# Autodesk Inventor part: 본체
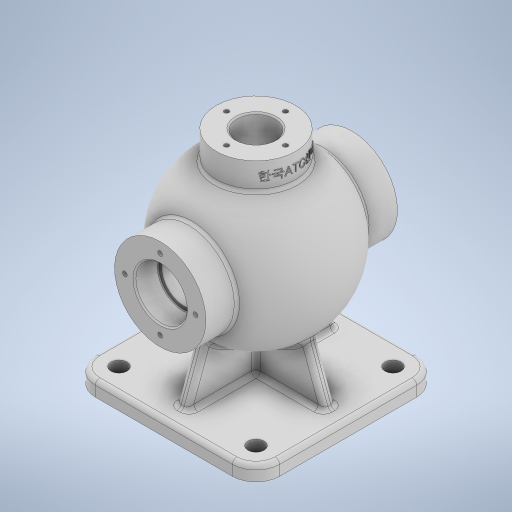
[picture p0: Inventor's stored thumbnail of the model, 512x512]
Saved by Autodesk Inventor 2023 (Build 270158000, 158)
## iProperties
Created: 2023-07
Part Number: 본체
Material: 일반
Document SubType Name: Modeling
Designer: Owner
Density: 1 g/cm^3
Appearance: 기본값
Author: Owner
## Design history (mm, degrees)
sketch "스케치1"
  geometry: L1 (-62.5, 62.5)-(62.5, 62.5); L2 (62.5, 62.5)-(62.5, -62.5); L3 (62.5, -62.5)-(-62.5, -62.5); L4 (-62.5, -62.5)-(-62.5, 62.5); L5 (-62.5, 62.5)-(62.5, -62.5); L6 (62.5, 62.5)-(-62.5, -62.5); 1 further point
  constraints: 12 end point, 2 midpoint, 2 parallel, 1 horizontal, 1 perpendicular
  dimensions: "d0" = 125 distance of L2.end L3.end; "d1" = 125 distance of L1.end L2.end
extrude "돌출1" new body sketch "스케치1" distance "d2" = 10; taper "d3" = 0 deg
fillet "모깎기1" dims "d4" = 16
fillet "모깎기2" dims "d5" = 3
sketch "스케치2"
  geometry: L1 (7, -62.5)-(0, -62.5) reference; L2 (0, -62.5)-(0, 62.5) reference; L3 (0, 62.5)-(7, 62.5) reference; L4 (10, 59.5)-(10, -59.5) reference; L5 (85, 65)-(85, -65); L6 (85, 65)-(116, 65); L7 (116, 65)-(116, 44.215); L8 (116, -44.215)-(116, -65); L9 (116, -65)-(85, -65); A1 r 3 centre (7, -59.5) between (7, -62.5) and (10, -59.5) reference; A2 r 3 centre (7, 59.5) between (10, 59.5) and (7, 62.5) reference; A3 r 54 centre (85, 0) between (116, -44.215) and (116, 44.215); 3 further points
  constraints: 10 end point, 2 midpoint, 2 perpendicular, 2 point on circle, 2 vertical, 1 centre point, 1 coincident, 1 horizontal, 1 horizontal alignment
  dimensions: "d6" = 130 distance of L5.start L5.end; "d7" = 85 distance between parallel lines of L2 L5; "d8" = 54 radius of A3; "d9" = 62 diameter of L7 L5; "d10" = 62 diameter of L8 L5
revolve "회전1" sketch "스케치2" stored, may be unused: angle "d11" = 90 deg
sketch "스케치3"
  geometry: L1 (7, -62.5)-(0, -62.5) reference; L2 (0, -62.5)-(0, 62.5) reference; L3 (0, 62.5)-(7, 62.5) reference; L4 (10, 59.5)-(10, -59.5) reference; L5 (54, 65)-(116, 65) reference; L6 (116, 65)-(116, 44.215) reference; L7 (116, -44.215)-(116, -65) reference; L8 (116, -65)-(54, -65) reference; L9 (54, -65)-(54, -44.215) reference; L10 (54, 44.215)-(54, 65) reference; L11 (10, 46.5)-(10, -46.5) reference; L12 (10, 50.5)-(55, 34.121); L13 (55, 34.121)-(55, -34.121); L14 (55, -34.121)-(10, -50.5); A1 r 3 centre (7, -59.5) between (7, -62.5) and (10, -59.5) reference; A2 r 3 centre (7, 59.5) between (10, 59.5) and (7, 62.5) reference; A3 r 54 centre (85, 0) between (116, -44.215) and (116, 44.215) reference; A4 r 54 centre (85, 0) between (54, 44.215) and (54, -44.215) reference; 7 further points
  constraints: 6 end point, 2 midpoint, 2 point on line, 1 equal length, 1 horizontal alignment, 1 parallel
  dimensions: "d12" = 20 deg angle of L12 L3; "d13" = 12 vertical distance of L2.end L12.start; "d14" = 55 distance between parallel lines of L2 L13
extrude "돌출2" join sketch "스케치3" stored distance "d15" = 8; taper "d16" = 0 deg
sketch "스케치4"
  geometry: L1 (-59.5, 10)-(-4, 10) reference; L2 (-4, 10)-(-4, 31.148) reference; L3 (4, 31.148)-(4, 10) reference; L4 (4, 10)-(59.5, 10) reference; L5 (62.5, 7)-(62.5, 0) reference; L6 (62.5, 0)-(-62.5, 0) reference; L7 (-62.5, 0)-(-62.5, 7) reference; L8 (-37.385, 46.034)-(-50.5, 10); L9 (-46.5, 10)-(46.5, 10) reference; A1 r 3 centre (-59.5, 7) between (-59.5, 10) and (-62.5, 7) reference; A2 r 3 centre (59.5, 7) between (62.5, 7) and (59.5, 10) reference; A3 r 54 centre (0, 85) between (4, 31.148) and (-4, 31.148) reference; 1 further point
  constraints: 2 end point, 1 point on circle, 1 point on line
  dimensions: "d17" = 20 deg angle of L7 L8; "d18" = 12 distance from line of L7 L8.end
feature "리브1" sketch "스케치4" dims "d19" = 1, "d20" = 8, "d21" = 0, "d22" = 0, "d23" = 1, "d24" = 1
fillet "모깎기3" dims "d25" = 3
fillet "모깎기4" dims "d26" = 3
fillet "모깎기5" dims "d27" = 3
sketch "스케치5"
  geometry: L1 (0, -62.5)-(0, 62.5) reference; L2 (0, 62.5)-(7, 62.5) reference; L3 (10, 59.5)-(10, 52.601) reference; L4 (11.974, 49.782)-(44.231, 38.041) reference; L5 (54, 45.749)-(54, 65) reference; L6 (54, 65)-(116, 65) reference; L7 (116, 65)-(116, 45.749) reference; L8 (116, -45.749)-(116, -65) reference; L9 (116, -65)-(54, -65) reference; L10 (54, -65)-(54, -45.749) reference; L11 (44.231, -38.041)-(11.974, -49.782) reference; L12 (10, -52.601)-(10, -59.5) reference; L13 (7, -62.5)-(0, -62.5) reference; L14 (54, 65)-(116, 65) reference; L15 (85, 65)-(85, -65); L16 (54, -65)-(116, -65) reference; L17 (102.5, 65)-(102.5, 49); L18 (102.5, 49)-(100, 49); L19 (100, 49)-(100, 41.364); L20 (100, -41.364)-(100, -49); L21 (100, -49)-(102.5, -49); L22 (102.5, -49)-(102.5, -65); A1 r 3 centre (7, 59.5) between (10, 59.5) and (7, 62.5) reference; A2 r 3 centre (13, 52.601) between (10, 52.601) and (11.974, 49.782) reference; A3 r 3 centre (45.257, 40.86) between (44.231, 38.041) and (47.349, 38.709) reference; A4 r 54 centre (85, 0) between (52.789, 43.341) and (47.349, 38.709) reference; A5 r 3 centre (51, 45.749) between (52.789, 43.341) and (54, 45.749) reference; A6 r 3 centre (119, 45.749) between (116, 45.749) and (117.211, 43.341) reference; A7 r 54 centre (85, 0) between (117.211, -43.341) and (117.211, 43.341) reference; A8 r 3 centre (119, -45.749) between (117.211, -43.341) and (116, -45.749) reference; A9 r 3 centre (51, -45.749) between (54, -45.749) and (52.789, -43.341) reference; A10 r 54 centre (85, 0) between (47.349, -38.709) and (52.789, -43.341) reference; A11 r 3 centre (45.257, -40.86) between (47.349, -38.709) and (44.231, -38.041) reference; A12 r 3 centre (13, -52.601) between (11.974, -49.782) and (10, -52.601) reference; A13 r 3 centre (7, -59.5) between (7, -62.5) and (10, -59.5) reference; A14 r 44 centre (85, 0) between (100, -41.364) and (100, 41.364); 5 further points
  constraints: 14 end point, 5 perpendicular, 2 equal length, 2 midpoint, 2 point on circle, 2 point on line, 2 vertical, 1 centre point, 1 vertical alignment
  dimensions: "d28" = 44 radius of A14; "d29" = 16 distance of L17.start L17.end; "d30" = 35 diameter of L17 L15; "d31" = 30 diameter of L19 L15
revolve "회전2" sketch "스케치5" stored, may be unused: angle "d32" = 90 deg
node "작업 평면1"
sketch "스케치6"
  geometry: C1 r 27 at (0, 0); C2 r 13 at (0, 0); 1 further point
  constraints: 2 centre point, 2 coincident
  dimensions: "d34" = 54 diameter of C1; "d35" = 26 diameter of C2
extrude "돌출3" join sketch "스케치6" stored distance "d36" = 8; taper "d37" = 0 deg
extrude "돌출4" cut sketch "스케치6" stored distance "d38" = 10; taper "d39" = 0 deg
fillet "모깎기6" dims "d40" = 3
chamfer "모따기1" distance "d41" = 1; stored, may be unused: second distance "d42" = 2, angle "d43" = 45 deg
sketch "스케치7"
  geometry: C1 r 5.5 at (-46.5, 46.5); C2 r 5.5 at (-46.5, -46.5); A1 r 13 centre (-46.5, 46.5) between (-46.5, 59.5) and (-59.5, 46.5) reference; A2 r 13 centre (-46.5, -46.5) between (-59.5, -46.5) and (-46.5, -59.5) reference; 1 further point
  constraints: 2 centre point, 2 coincident, 1 equal radius
  dimensions: "d44" = 11 diameter of C1
extrude "돌출5" cut sketch "스케치7" extent not by distance; stored distance "d45" = 0; taper "d46" = 0 deg
sketch "스케치8"
  geometry: C1 r 31 at (0, 0) reference; 2 further points
  constraints: 1 vertical alignment
  dimensions: "d47" = 24 distance of C1.centre point (0, 24)
hole "구멍1" sketch "스케치8" at (0, 24) diameter "d48" = 3.242; stored, may be unused: countersink angle "d52" = 90 deg, drill point angle "d54" = 118 deg; dims "d49" = 12, "d50" = 4, "d51" = 2, "d53" = 15
sketch "스케치9"
  geometry: C1 r 27 at (0, 0) reference; 1 further point
  constraints: 1 vertical alignment
  dimensions: "d58" = 20 distance of C1.centre point (0, 20)
hole "구멍2" sketch "스케치9" at (0, 20) diameter "d59" = 3.242; stored, may be unused: countersink angle "d63" = 90 deg, drill point angle "d65" = 118 deg; dims "d60" = 9, "d61" = 4, "d62" = 2, "d64" = 11
node "작업 평면2"
sketch "스케치10"
  geometry: L1 (-150, -62.5)-(-150, 62.5) reference; L2 (-150, 62.5)-(-143, 62.5) reference; L3 (-140, 59.5)-(-140, 7) reference; L4 (-137, 4)-(-114.709, 4) reference; L5 (-80.232, 45.749)-(-80.232, 65) reference; L6 (-80.232, 65)-(-49.768, 65) reference; L7 (-49.768, 65)-(-49.768, 45.749) reference; L8 (-49.768, -45.749)-(-49.768, -65) reference; L9 (-49.768, -65)-(-80.232, -65) reference; L10 (-80.232, -65)-(-80.232, -45.749) reference; L11 (-114.709, -4)-(-137, -4) reference; L12 (-140, -7)-(-140, -59.5) reference; L13 (-143, -62.5)-(-150, -62.5) reference; L14 (0, 0)-(-16.534, 0) reference; L15 (0, -27)-(0, 27) reference; C1 r 34.742 at (-65, 0) reference; A1 r 3 centre (-143, 59.5) between (-140, 59.5) and (-143, 62.5) reference; A2 r 3 centre (-137, 7) between (-140, 7) and (-137, 4) reference; A3 r 46.765 centre (-65, 0) between (-82.565, 43.341) and (-111.293, 6.632) reference; A4 r 46.765 centre (-65, 0) between (-19.084, 8.874) and (-47.435, 43.341) reference; A5 r 46.765 centre (-65, 0) between (-47.435, -43.341) and (-19.084, -8.874) reference; A6 r 46.765 centre (-65, 0) between (-111.293, -6.632) and (-82.565, -43.341) reference; A7 r 3 centre (-137, -7) between (-137, -4) and (-140, -7) reference; A8 r 3 centre (-143, -59.5) between (-143, -62.5) and (-140, -59.5) reference; 2 further points
  constraints: 1 horizontal alignment, 9 other
  dimensions: "d69" = 9 distance from line of L15 point (-9, 0)
feature "엠보싱1" sketch "스케치10" dims "d0" = 125, "d1" = 125, "d70" = 0.5, "d71" = 0
fillet "모깎기7" dims "d72" = 0.6
feature "Ǌ耀ǌ耀ǎ耀ǐ耀ǒ耀ǔ耀ǖ耀ǘ耀" dims "d0" = 125, "d1" = 125, "d2" = 10, "d3" = 0, "d4" = 16, "d5" = 3, "d6" = 130, "d7" = 85, "d8" = 54, "d9" = 62, "d10" = 62, "d11" = 90 deg, "d12" = 20 deg, "d13" = 12, "d14" = 55, "d15" = 8, "d16" = 0, "d17" = 20 deg, "d18" = 12, "d19" = 1, "d20" = 8, "d21" = 0, "d22" = 0, "d23" = 1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
node "솔리드1"
mirror "미러1"
mirror "미러2"
pattern_circular "원형 패턴1" dims angle "d56" = 360 deg
mirror "미러3"
pattern_circular "원형 패턴2" dims angle "d67" = 360 deg
node "절단 모서리 투영1"
node "절단 모서리 투영2"
node "절단 모서리 투영3"
node "절단 모서리 투영4"
node "절단 모서리 투영5"
feature "A9D066F2-1C7D-4E18-AEED-F7BC21143FA4" dims "d48" = 3.242, "d49" = 12, "d50" = 4, "d51" = 2, "d52" = 90 deg, "d53" = 15, "d54" = 118 deg
